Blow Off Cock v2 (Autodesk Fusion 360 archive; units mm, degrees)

design "Blow Off Cock" references "Stud", "Cock", "Nut", "Gland", "Body"
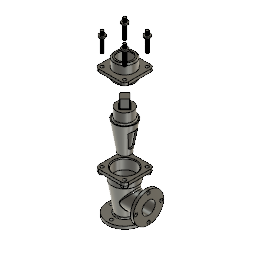
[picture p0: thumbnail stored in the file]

design "Nut"
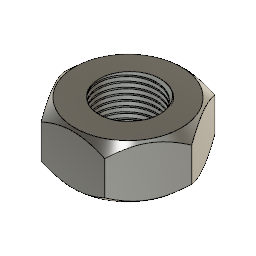
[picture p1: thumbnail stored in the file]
sketch "Sketch1" plane through (0, 0, 0) normal (0, 0, 1) x axis (1, 0, 0)
  line L1 (-12, 0) -> (-6, 10.3923)
  line L2 (-6, -10.3923) -> (-12, 0)
  line L3 (6, -10.3923) -> (-6, -10.3923)
  line L4 (12, 0) -> (6, -10.3923)
  line L5 (6, 10.3923) -> (12, 0)
  line L6 (-6, 10.3923) -> (6, 10.3923)
  circle C1 centre (0, 0) radius 6
  point P1 (0, 0)
  point P2 (0, 0)
  point P9 (0, 0)
  point P4 (-12, 0)
  point P7 (12, 0)
  point P3 (-6, 10.3923)
  point P8 (6, 10.3923)
  coincident P1 P2
  coincident P2 P9
  horizontal P4 P7
  dimension "d1" diameter C1 = 12
  dimension "d2" distance P3 P8 = 12
extrude "Extrude1" new body sketch "Sketch1" distance 10
sketch "Sketch2" plane through (0, 0, 5) normal (0, 0, 1) x axis (-1, 0, 0)
  line L1 (6, -10.3923) -> (-6, -10.3923)
  line L2 (12, 0) -> (6, -10.3923)
  line L3 (6, 10.3923) -> (12, 0)
  line L4 (-6, 10.3923) -> (6, 10.3923)
  line L5 (-12, 0) -> (-6, 10.3923)
  line L6 (-6, -10.3923) -> (-12, 0)
  circle C1 centre (0, 0) radius 6
  circle C2 centre (0, 0) radius 10
  point P1 (0, 0)
  point P9 (0, 0)
  coincident P1 P9
  dimension "d5" diameter C2 = 20
extrude "Extrude2" sketch "Sketch2" profile of C1 C2 no distance stored taper 48
mirror "Mirror1"
thread "Thread1"

design "Cock"
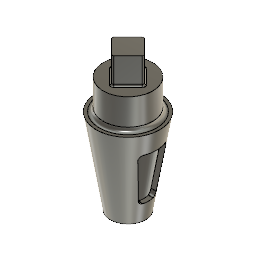
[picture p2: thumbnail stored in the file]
sketch "Sketch1" plane through (0, 0, 0) normal (0, 1, 0) x axis (1, 0, 0)
  line L1 (23, 0) -> (17, 0)
  line L2 (41, -110) -> (23, 0)
  line L3 (0, -144.3099) -> (0, 0)
  line L4 (17, 0) -> (34.0182, -104)
  line L5 (37.7698, 0) -> (0, 0)
  line L6 (32, -110) -> (41, -110)
  line L7 (32, -149) -> (32, -110)
  line L8 (26, -104) -> (34.0182, -104)
  line L9 (26, -143) -> (26, -104)
  line L10 (0, -149) -> (32, -149)
  line L11 (0, -143) -> (26, -143)
  line L12 (0, -143) -> (0, -149)
  point P1 (0, 0)
  point P4 (0, 0)
  point P8 (0, 0)
  point P7 (17, 0)
  point P14 (0, -149)
  point P15 (0, -143)
  point P3 (41, -110)
  horizontal L1
  coincident P1 P4
  perpendicular L1 L3
  parallel L2 L4
  coincident P1 P8
  perpendicular L3 L5
  horizontal P1 P7
  horizontal L6
  perpendicular L6 L7
  horizontal L8
  perpendicular L8 L9
  perpendicular L7 L10
  coincident L3 P14
  coincident L3 P15
  perpendicular L3 L11
  dimension "d1" = 46
  dimension "d2" = 34
  dimension "d3" distance L1 P3 = 110
  dimension "d4" = 82
  dimension "d5" distance L6 L8 = 6
  dimension "d7" = 64
  dimension "d8" distance L7 L9 = 6
  dimension "d9" distance L5 L10 = 149
  dimension "d10" distance L10 L11 = 6
revolve "Revolve1" sketch "Sketch1" AlongAngle 360
sketch "Sketch2" plane through (0, 0, 149) normal (0, 0, 1) x axis (-1, 0, 0)
  line L1 (21.2132, 0) -> (0, -21.2132)
  line L2 (0, 21.2132) -> (21.2132, 0)
  line L3 (-21.2132, 0) -> (0, 21.2132)
  line L4 (0, -21.2132) -> (-21.2132, 0)
  point P1 (0, 0)
  point P3 (21.2132, 0)
  point P5 (-21.2132, 0)
  point P2 (0, -21.2132)
  point P4 (0, 21.2132)
  perpendicular L2 L3
  horizontal P1 P3
  horizontal P1 P5
  vertical P1 P2
  vertical P1 P4
  equal L1 L2
  equal L1 L4
  dimension "d28" distance P2 P5 = 30
extrude "Extrude1" add sketch "Sketch2" along normal blind 34
fillet "Fillet1" radius 2
fillet "Fillet2" radius 2
fillet "Fillet3" radius 5
fillet "Fillet4" radius 5
sketch "Sketch5" plane through (0, 0, 0) normal (1, 0, 0) x axis (0, 1, 0)
  line L1 (-23, 0) -> (23, 0)
  line L2 (0, 97.021) -> (0, 0)
  line L3 (13.3134, 85) -> (-13.3134, 85)
  line L4 (11.5626, 27.3601) -> (18.2723, 79.3601)
  line L5 (-6.6037, 23) -> (6.6037, 23)
  line L6 (-18.2723, 79.3601) -> (-11.5626, 27.3601)
  line L7 (-41, 110) -> (41, 110)
  arc A1 centre (-13.3134, 80) radius 5 clockwise from (-18.2723, 79.3601) to (-13.3134, 85)
  arc A2 centre (13.3134, 80) radius 5 clockwise from (13.3134, 85) to (18.2723, 79.3601)
  arc A3 centre (6.6037, 28) radius 5 clockwise from (11.5626, 27.3601) to (6.6037, 23)
  arc A4 centre (-6.6037, 28) radius 5 clockwise from (-6.6037, 23) to (-11.5626, 27.3601)
  point P1 (0, 0)
  point P4 (0, 0)
  point P6 (-19, 85)
  point P7 (19, 85)
  point P8 (11, 23)
  point P9 (-11, 23)
  coincident P1 P4
  perpendicular L1 L2
  perpendicular L2 L3
  perpendicular L2 L5
  symmetric L2 P6 P7
  symmetric L2 P8 P9
  coincident P6 L6
  tangent L3 A1
  tangent L6 A1
  coincident P7 L4
  coincident P7 L3
  tangent L4 A2
  tangent L3 A2
  equal A1 A2
  coincident P8 L4
  tangent L4 A3
  tangent L5 A3
  equal A1 A3
  coincident P9 L5
  coincident P9 L6
  tangent L5 A4
  tangent L6 A4
  equal A1 A4
  dimension "d36" distance L3 L5 = 62
  dimension "d37" distance L3 L7 = 25
  dimension "d38" distance P6 P7 = 38
  dimension "d39" distance P8 P9 = 22
  dimension "d40" radius A1 = 5
extrude "Extrude4" cut sketch "Sketch5" profile of L3 L4 L5 L6 A1 A2 A3 A4 no distance stored
sketch "Sketch4" plane through (0, 0, 143) normal (0, 0, -1) x axis (1, 0, 0)
  circle C1 centre (0, 0) radius 26
  circle C2 centre (0, 0) radius 12
  point P1 (0, 0)
  point P3 (0, 0)
  coincident P1 P3
  dimension "d31" diameter C2 = 24
extrude "Extrude3" cut sketch "Sketch4" profile of C2 against normal blind 32
fillet "Fillet5" radius 5
fillet "Fillet6" radius 5

design "Gland"
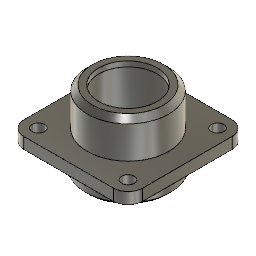
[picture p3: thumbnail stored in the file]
sketch "Sketch1" plane through (0, 0, 0) normal (0, 0, 1) x axis (1, 0, 0)
  circle C1 centre (0, 0) radius 41
  point P1 (0, 0)
  point P2 (0, 0)
  coincident P1 P2
  dimension "d1" diameter C1 = 82
extrude "Extrude1" new body sketch "Sketch1" along normal blind 25
sketch "Sketch2" plane through (0, 0, 25) normal (0, 0, 1) x axis (-1, 0, 0)
  line L1 (57, -57) -> (-57, -57)
  line L2 (57, 57) -> (57, -57)
  line L3 (-57, 57) -> (57, 57)
  line L4 (-57, -57) -> (-57, 57)
  line L5 (57, 57) -> (-57, -57)
  line L6 (-57, 57) -> (57, -57)
  circle C1 centre (0, 0) radius 41
  point P7 (0, 0)
  point P1 (0, 0)
  point P3 (-57, -57)
  point P4 (57, -57)
  point P5 (57, 57)
  horizontal L1
  perpendicular L1 L2
  parallel L1 L3
  parallel L2 L4
  coincident L5 P7
  coincident L6 P7
  coincident P1 P7
  dimension "d4" distance P3 P4 = 114
  dimension "d5" distance P4 P5 = 114
extrude "Extrude2" add sketch "Sketch2" profile of C1 L1 L2 L3 L4 along normal blind 11
fillet "Fillet1" sketch "Sketch5" radius 14
sketch "Sketch3" plane through (0, 0, 36) normal (0, 0, 1) x axis (-1, 0, 0)
  line L1 (43, -57) -> (-43, -57)
  line L2 (57, 43) -> (57, -43)
  line L3 (-43, 57) -> (43, 57)
  line L4 (-57, -43) -> (-57, 43)
  arc A1 centre (-43, -43) radius 14 clockwise from (-43, -57) to (-57, -43)
  arc A2 centre (43, -43) radius 14 clockwise from (57, -43) to (43, -57)
  arc A3 centre (43, 43) radius 14 clockwise from (43, 57) to (57, 43)
  arc A4 centre (-43, 43) radius 14 clockwise from (-57, 43) to (-43, 57)
  circle C1 centre (0, 0) radius 39
  point P1 (0, 0)
  point P14 (0, 0)
  coincident P1 P14
  dimension "d9" diameter C1 = 78
extrude "Extrude3" add sketch "Sketch3" profile of C1 along normal blind 36
chamfer "Chamfer1" distance 5 rotateAngle 45
sketch "Sketch4" plane through (0, 0, 0) normal (0, 1, 0) x axis (1, 0, 0)
  line L1 (-34, -72) -> (34, -72)
  line L2 (0, -90.6958) -> (0, 0)
  line L3 (-28, -72) -> (0, -72)
  line L4 (-28, -67) -> (-28, -72)
  line L5 (39, -67) -> (-39, -67)
  line L6 (-34, -67) -> (-28, -67)
  line L7 (-34, -21) -> (-34, -67)
  line L8 (-32, -21) -> (-34, -21)
  line L9 (41, 0) -> (-41, 0)
  line L10 (-32, 0) -> (-32, -21)
  line L11 (0, 0) -> (-32, 0)
  line L12 (0, -72) -> (0, 0)
  point P1 (0, 0)
  point P4 (0, 0)
  point P6 (0, -72)
  point P11 (-34, -67)
  point P16 (-32, 0)
  point P7 (-28, -72)
  point P17 (0, 0)
  point P18 (0, 0)
  point P8 (-28, -67)
  point P13 (-32, -21)
  coincident P1 P4
  perpendicular L1 L2
  coincident L2 P6
  perpendicular L2 L3
  perpendicular L3 L4
  coincident L5 P11
  perpendicular L4 L6
  perpendicular L5 L7
  perpendicular L7 L8
  coincident L9 P16
  perpendicular L5 L10
  coincident L1 P7
  coincident P1 P17
  coincident P1 P18
  dimension "d15" distance L2 L4 = 28
  dimension "d16" distance L1 P8 = 5
  dimension "d17" distance L2 L7 = 34
  dimension "d18" distance L2 L10 = 32
  dimension "d19" distance P13 P16 = 21
revolve "Revolve1" sketch "Sketch4" AlongAngle 360
sketch "Sketch5" plane through (0, 0, 36) normal (0, 0, 1) x axis (-1, 0, 0)
  line L1 (43, -57) -> (-43, -57)
  line L2 (57, 43) -> (57, -43)
  line L3 (-43, 57) -> (43, 57)
  line L4 (-57, -43) -> (-57, 43)
  circle C1 centre (0, 0) radius 39
  arc A1 centre (-43, -43) radius 14 clockwise from (-43, -57) to (-57, -43)
  arc A2 centre (43, -43) radius 14 clockwise from (57, -43) to (43, -57)
  arc A3 centre (43, 43) radius 14 clockwise from (43, 57) to (57, 43)
  arc A4 centre (-43, 43) radius 14 clockwise from (-57, 43) to (-43, 57)
  circle C2 centre (43, 43) radius 6
  concentric A3 C2
  dimension "d26" diameter C2 = 12
extrude "Extrude4" cut sketch "Sketch5" profile of C2 to an object
rectangular_pattern "R-Pattern1" uSpaceDistance 86 vSpaceDistance 86
chamfer "Chamfer2" distance 3 rotateAngle 45

design "Stud"
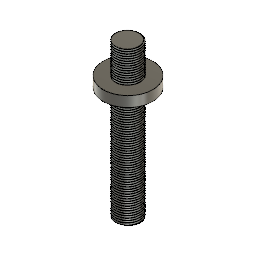
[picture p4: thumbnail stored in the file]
sketch "Sketch1" plane through (0, 0, 0) normal (0, 0, 1) x axis (1, 0, 0)
  circle C1 centre (0, 0) radius 6
  point P1 (0, 0)
  point P2 (0, 0)
  coincident P1 P2
  dimension "d1" diameter C1 = 12
extrude "Extrude1" new body sketch "Sketch1" along normal blind 54
sketch "Sketch2" plane through (0, 0, 54) normal (0, 0, 1) x axis (-1, 0, 0)
  circle C1 centre (0, 0) radius 6
  circle C2 centre (0, 0) radius 12
  point P1 (0, 0)
  point P3 (0, 0)
  coincident P1 P3
  dimension "d4" diameter C2 = 24
extrude "Extrude2" add sketch "Sketch2" along normal blind 5
sketch "Sketch3" plane through (0, 0, 59) normal (0, 0, 1) x axis (-1, 0, 0)
  circle C1 centre (0, 0) radius 12
  circle C2 centre (0, 0) radius 6
  point P1 (0, 0)
  point P3 (0, 0)
  coincident P1 P3
  dimension "d7" diameter C2 = 12
extrude "Extrude3" add sketch "Sketch3" profile of C2 along normal blind 15
thread "Thread1"
thread "Thread2"

design "Body"
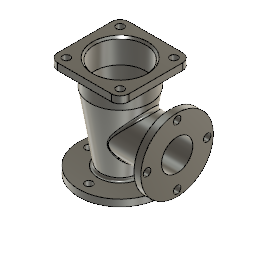
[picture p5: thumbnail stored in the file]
sketch "Sketch1" plane through (0, 0, 0) normal (0, 1, 0) x axis (1, 0, 0)
  line L1 (0, -187.0761) -> (0, 0)
  line L2 (30, -22) -> (30, 0)
  line L3 (17.5, 0) -> (30, 0)
  line L4 (17.5, -33) -> (17.5, 0)
  line L5 (66, -22) -> (30, -22)
  line L6 (66, -33) -> (66, -22)
  line L7 (30, -33) -> (66, -33)
  line L8 (48, -143) -> (30, -33)
  line L9 (48, -171) -> (48, -143)
  line L10 (41, -171) -> (48, -171)
  line L11 (41, -143) -> (41, -171)
  line L12 (23, -33) -> (41, -143)
  line L13 (23, -33) -> (17.5, -33)
  point P1 (0, 0)
  point P2 (0, 0)
  point P4 (30, 0)
  point P15 (23, -33)
  point P16 (23, -33)
  point P5 (30, -22)
  point P11 (48, -143)
  point P12 (48, -171)
  point P6 (17.5, 0)
  point P7 (17.5, -33)
  coincident P1 P2
  vertical L1
  parallel L1 L2
  horizontal P1 P4
  perpendicular L2 L3
  perpendicular L3 L4
  perpendicular L2 L5
  perpendicular L5 L6
  perpendicular L6 L7
  vertical L9
  perpendicular L9 L10
  perpendicular L10 L11
  equal L9 L11
  parallel L8 L12
  perpendicular L4 L13
  coincident P15 P16
  dimension "d1" = 60
  dimension "d2" = 35
  dimension "d3" distance P4 P5 = 22
  dimension "d5" = 132
  dimension "d7" = 60
  dimension "d8" = 96
  dimension "d9" distance L7 P11 = 110
  dimension "d10" distance P11 P12 = 28
  dimension "d11" = 82
  dimension "d12" distance L3 L7 = 33
  dimension "d13" distance P6 P7 = 33
revolve "Revolve1" sketch "Sketch1" AlongAngle 360
work_plane "WorkPlane1" AlongDistance 80
sketch "Sketch2" plane through (80, 0, 0) normal (1, 0, 0) x axis (0, 1, 0)
  circle C1 centre (0, 93) radius 36
  point P1 (0, 0)
  point P2 (0, 93)
  vertical P1 P2
  dimension "d16" diameter C1 = 72
  dimension "d17" distance P1 P2 = 93
extrude "Extrude1" add sketch "Sketch2" to an object
sketch "Sketch3" plane through (80, 0, 0) normal (1, 0, 0) x axis (0, 1, 0)
  circle C1 centre (0, 93) radius 36
  circle C2 centre (0, 93) radius 25
  concentric C1 C2
  dimension "d24" diameter C2 = 50
extrude "Extrude2" cut sketch "Sketch3" profile of C2 to an object
sketch "Sketch4" plane through (80, 0, 0) normal (1, 0, 0) x axis (0, 1, 0)
  circle C1 centre (0, 93) radius 25
  circle C2 centre (0, 93) radius 36
  circle C3 centre (0, 93) radius 25
  circle C4 centre (0, 93) radius 58
  concentric C1 C3
  concentric C1 C4
  equal C1 C3
  dimension "d25" diameter C4 = 116
extrude "Extrude3" add sketch "Sketch4" along normal blind 11
sketch "Sketch5" plane through (0, 0, 171) normal (0, 0, 1) x axis (-1, 0, 0)
  line L1 (57, -57) -> (-57, -57)
  line L2 (57, 57) -> (57, -57)
  line L3 (-57, 57) -> (57, 57)
  line L4 (-57, -57) -> (-57, 57)
  line L5 (57, 57) -> (-57, -57)
  line L6 (-57, 57) -> (57, -57)
  circle C1 centre (0, 0) radius 48
  circle C2 centre (0, 0) radius 41
  circle C3 centre (0, 0) radius 41
  point P7 (0, 0)
  point P1 (0, 0)
  point P8 (0, 0)
  point P4 (57, -57)
  point P5 (57, 57)
  point P3 (-57, -57)
  horizontal L1
  perpendicular L1 L2
  parallel L1 L3
  parallel L2 L4
  coincident L5 P7
  coincident L6 P7
  coincident P1 P7
  coincident P7 P8
  equal C2 C3
  dimension "d28" distance P4 P5 = 114
  dimension "d29" distance P3 P4 = 114
extrude "Extrude4" add sketch "Sketch5" profile of C1 C2 L1 L2 L3 L4 C3 along normal blind 11
fillet "Fillet1" radius 14
sketch "Sketch6" plane through (0, 0, 182) normal (0, 0, 1) x axis (-1, 0, 0)
  line L1 (43, -57) -> (-43, -57)
  line L2 (57, 43) -> (57, -43)
  line L3 (-43, 57) -> (43, 57)
  line L4 (-57, -43) -> (-57, 43)
  arc A1 centre (-43, -43) radius 14 clockwise from (-43, -57) to (-57, -43)
  arc A2 centre (43, -43) radius 14 clockwise from (57, -43) to (43, -57)
  arc A3 centre (43, 43) radius 14 clockwise from (43, 57) to (57, 43)
  arc A4 centre (-43, 43) radius 14 clockwise from (-57, 43) to (-43, 57)
  circle C1 centre (0, 0) radius 41
  circle C2 centre (43, 43) radius 6
  circle C3 centre (43, -43) radius 6
  circle C4 centre (-43, -43) radius 6
  circle C5 centre (-43, 43) radius 6
  concentric A3 C2
  concentric A2 C3
  concentric A1 C4
  concentric A4 C5
  equal C2 C3
  equal C3 C4
  equal C4 C5
  dimension "d33" diameter C2 = 12
extrude "Extrude5" cut sketch "Sketch6" profile of C2 C3 C4 C5 to an object
sketch "Sketch7" plane through (0, 0, 33) normal (0, 0, 1) x axis (-1, 0, 0)
  circle C1 centre (0, 0) radius 66
  circle C2 centre (0, 0) radius 30
  circle C3 centre (0, 50) radius 6
  point P1 (0, 0)
  point P3 (0, 50)
  vertical P1 P3
  dimension "d38" diameter C3 = 12
  dimension "d39" distance P1 P3 = 50
extrude "Extrude6" cut sketch "Sketch7" profile of C3 to an object
circular_pattern "C-Pattern1" TotalAngle 360
fillet "Fillet2" radius 4
chamfer "Chamfer1" distance 3 rotateAngle 45
sketch "Sketch9" plane through (91, 0, 0) normal (1, 0, 0) x axis (0, 1, 0)
  line L1 (-65.6451, 93) -> (0, 93)
  circle C1 centre (0, 93) radius 25
  circle C2 centre (0, 93) radius 58
  circle C3 centre (-48, 93) radius 6
  point P2 (0, 93)
  point P4 (0, 93)
  point P3 (-48, 93)
  coincident P2 P4
  horizontal L1
  coincident P3 L1
  dimension "d48" diameter C3 = 12
  dimension "d49" distance P3 P4 = 48
extrude "Extrude7" cut sketch "Sketch9" profile of C3 to an object
circular_pattern "C-Pattern2" TotalAngle 360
